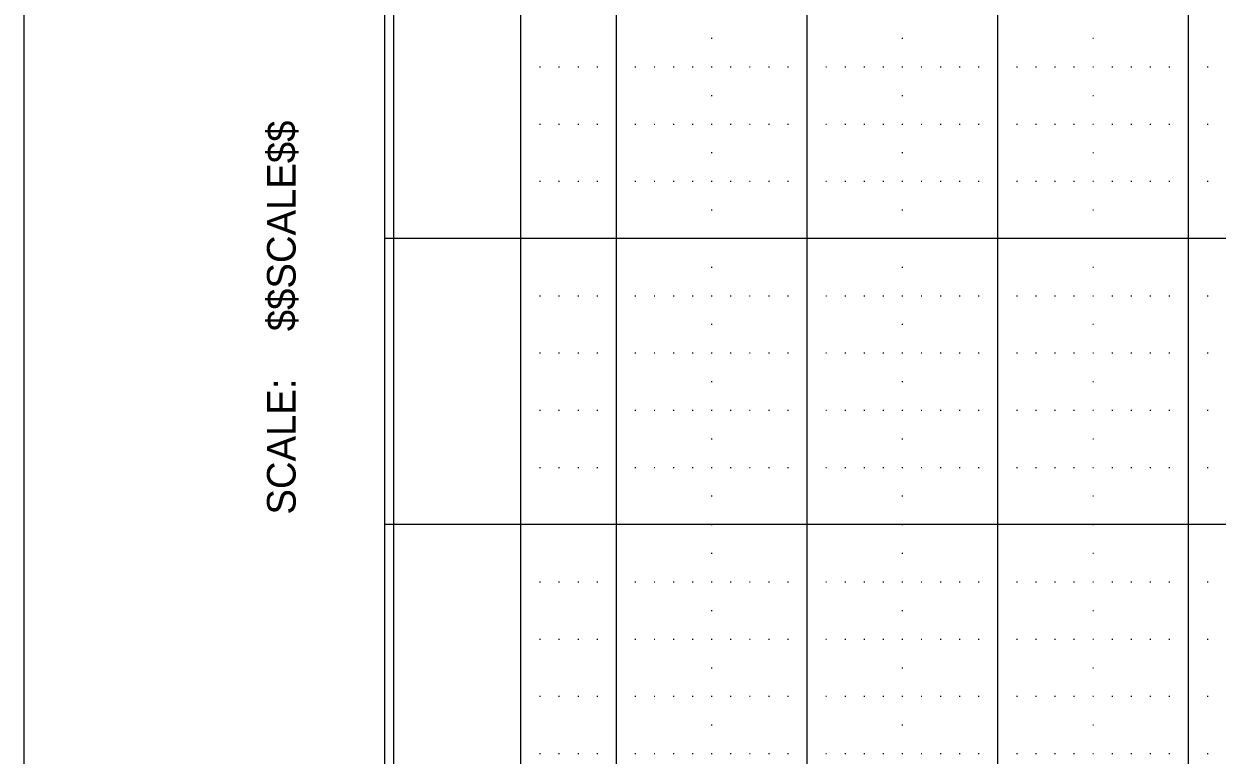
# Model space of a CAD drawing. Extents: x -1.3 to 32, y -0.2 to 20.7.
# Drawn here: x -1.292 to 2.879, y 2.458 to 5.014 of the extents above; entities that cross this region are included whole.
import ezdxf

# ---------------------------------------------------------------- set-up
doc = ezdxf.new("R2010")
doc.units = 0
for name, color, linetype in [('Level 1', 7, 'Continuous'), ('Level 37', 7, 'Continuous'), ('Level 4', 7, 'Continuous'), ('Level 5', 7, 'Continuous'), ('Level 62', 7, 'Continuous'), ('Level 63', 7, 'Continuous')]:
    doc.layers.add(name, color=color, linetype=linetype)

msp = doc.modelspace()

# ---------------------------------------------------------------- linework, layer by layer
at = {"layer": 'Level 1'}
msp.add_line((-0.03, -0.03), (-0.03, 20.516), dxfattribs=at)
at = {"layer": 'Level 37'}
msp.add_line((0.4457, 0.2635), (0.4457, 10.264), dxfattribs=at)
at = {"layer": 'Level 4'}
for p, q in [((0.4457, 0.264), (0.4457, 10.264)), ((0.779, 0.264), (0.779, 10.264)), ((1.4457, 0.264), (1.4457, 10.264)), ((2.1123, 0.264), (2.1123, 10.264)), ((2.779, 0.264), (2.779, 10.264)), ((31.588, 4.264), (-0.03, 4.264)), ((31.588, 3.264), (-0.03, 3.264))]:
    msp.add_line(p, q, dxfattribs=at)
at = {"layer": 'Level 5'}
for p, q in [((1.1107, 4.964), (1.114, 4.964)), ((1.7773, 4.964), (1.7807, 4.964)), ((2.444, 4.964), (2.4473, 4.964)), ((0.5107, 4.864), (0.514, 4.864)), ((0.5773, 4.864), (0.5807, 4.864)), ((0.644, 4.864), (0.6473, 4.864)), ((0.7107, 4.864), (0.714, 4.864)), ((0.844, 4.864), (0.8473, 4.864)), ((0.9107, 4.864), (0.914, 4.864)), ((0.9773, 4.864), (0.9807, 4.864)), ((1.044, 4.864), (1.0473, 4.864)), ((1.1107, 4.864), (1.114, 4.864)), ((1.1773, 4.864), (1.1807, 4.864)), ((1.244, 4.864), (1.2473, 4.864)), ((1.3107, 4.864), (1.314, 4.864)), ((1.3773, 4.864), (1.3807, 4.864)), ((1.5107, 4.864), (1.514, 4.864)), ((1.5773, 4.864), (1.5807, 4.864)), ((1.644, 4.864), (1.6473, 4.864)), ((1.7107, 4.864), (1.714, 4.864)), ((1.7773, 4.864), (1.7807, 4.864)), ((1.844, 4.864), (1.8473, 4.864)), ((1.9107, 4.864), (1.914, 4.864)), ((1.9773, 4.864), (1.9807, 4.864)), ((2.044, 4.864), (2.0473, 4.864)), ((2.1773, 4.864), (2.1807, 4.864)), ((2.244, 4.864), (2.2473, 4.864)), ((2.3107, 4.864), (2.314, 4.864)), ((2.3773, 4.864), (2.3807, 4.864)), ((2.444, 4.864), (2.4473, 4.864)), ((2.5107, 4.864), (2.514, 4.864)), ((2.5773, 4.864), (2.5807, 4.864)), ((2.644, 4.864), (2.6473, 4.864)), ((2.7107, 4.864), (2.714, 4.864)), ((2.844, 4.864), (2.8473, 4.864)), ((1.1107, 4.764), (1.114, 4.764)), ((1.7773, 4.764), (1.7807, 4.764)), ((2.444, 4.764), (2.4473, 4.764)), ((0.5107, 4.664), (0.514, 4.664)), ((0.5773, 4.664), (0.5807, 4.664)), ((0.644, 4.664), (0.6473, 4.664)), ((0.7107, 4.664), (0.714, 4.664)), ((0.844, 4.664), (0.8473, 4.664)), ((0.9107, 4.664), (0.914, 4.664)), ((0.9773, 4.664), (0.9807, 4.664)), ((1.044, 4.664), (1.0473, 4.664)), ((1.1107, 4.664), (1.114, 4.664)), ((1.1773, 4.664), (1.1807, 4.664)), ((1.244, 4.664), (1.2473, 4.664)), ((1.3107, 4.664), (1.314, 4.664)), ((1.3773, 4.664), (1.3807, 4.664)), ((1.5107, 4.664), (1.514, 4.664)), ((1.5773, 4.664), (1.5807, 4.664)), ((1.644, 4.664), (1.6473, 4.664)), ((1.7107, 4.664), (1.714, 4.664)), ((1.7773, 4.664), (1.7807, 4.664)), ((1.844, 4.664), (1.8473, 4.664)), ((1.9107, 4.664), (1.914, 4.664)), ((1.9773, 4.664), (1.9807, 4.664)), ((2.044, 4.664), (2.0473, 4.664)), ((2.1773, 4.664), (2.1807, 4.664)), ((2.244, 4.664), (2.2473, 4.664)), ((2.3107, 4.664), (2.314, 4.664)), ((2.3773, 4.664), (2.3807, 4.664)), ((2.444, 4.664), (2.4473, 4.664)), ((2.5107, 4.664), (2.514, 4.664)), ((2.5773, 4.664), (2.5807, 4.664)), ((2.644, 4.664), (2.6473, 4.664)), ((2.7107, 4.664), (2.714, 4.664)), ((2.844, 4.664), (2.8473, 4.664)), ((1.1107, 4.564), (1.114, 4.564)), ((1.7773, 4.564), (1.7807, 4.564)), ((2.444, 4.564), (2.4473, 4.564)), ((0.5107, 4.464), (0.514, 4.464)), ((0.5773, 4.464), (0.5807, 4.464)), ((0.644, 4.464), (0.6473, 4.464)), ((0.7107, 4.464), (0.714, 4.464)), ((0.844, 4.464), (0.8473, 4.464)), ((0.9107, 4.464), (0.914, 4.464)), ((0.9773, 4.464), (0.9807, 4.464)), ((1.044, 4.464), (1.0473, 4.464)), ((1.1107, 4.464), (1.114, 4.464)), ((1.1773, 4.464), (1.1807, 4.464)), ((1.244, 4.464), (1.2473, 4.464)), ((1.3107, 4.464), (1.314, 4.464)), ((1.3773, 4.464), (1.3807, 4.464)), ((1.5107, 4.464), (1.514, 4.464)), ((1.5773, 4.464), (1.5807, 4.464)), ((1.644, 4.464), (1.6473, 4.464)), ((1.7107, 4.464), (1.714, 4.464)), ((1.7773, 4.464), (1.7807, 4.464)), ((1.844, 4.464), (1.8473, 4.464)), ((1.9107, 4.464), (1.914, 4.464)), ((1.9773, 4.464), (1.9807, 4.464)), ((2.044, 4.464), (2.0473, 4.464)), ((2.1773, 4.464), (2.1807, 4.464)), ((2.244, 4.464), (2.2473, 4.464)), ((2.3107, 4.464), (2.314, 4.464)), ((2.3773, 4.464), (2.3807, 4.464)), ((2.444, 4.464), (2.4473, 4.464)), ((2.5107, 4.464), (2.514, 4.464)), ((2.5773, 4.464), (2.5807, 4.464)), ((2.644, 4.464), (2.6473, 4.464)), ((2.7107, 4.464), (2.714, 4.464)), ((2.844, 4.464), (2.8473, 4.464)), ((1.1107, 4.364), (1.114, 4.364)), ((1.7773, 4.364), (1.7807, 4.364)), ((2.444, 4.364), (2.4473, 4.364)), ((1.1107, 4.164), (1.114, 4.164)), ((1.7773, 4.164), (1.7807, 4.164)), ((2.444, 4.164), (2.4473, 4.164)), ((0.5107, 4.064), (0.514, 4.064)), ((0.5773, 4.064), (0.5807, 4.064)), ((0.644, 4.064), (0.6473, 4.064)), ((0.7107, 4.064), (0.714, 4.064)), ((0.844, 4.064), (0.8473, 4.064)), ((0.9107, 4.064), (0.914, 4.064)), ((0.9773, 4.064), (0.9807, 4.064)), ((1.044, 4.064), (1.0473, 4.064)), ((1.1107, 4.064), (1.114, 4.064)), ((1.1773, 4.064), (1.1807, 4.064)), ((1.244, 4.064), (1.2473, 4.064)), ((1.3107, 4.064), (1.314, 4.064)), ((1.3773, 4.064), (1.3807, 4.064)), ((1.5107, 4.064), (1.514, 4.064)), ((1.5773, 4.064), (1.5807, 4.064)), ((1.644, 4.064), (1.6473, 4.064)), ((1.7107, 4.064), (1.714, 4.064)), ((1.7773, 4.064), (1.7807, 4.064)), ((1.844, 4.064), (1.8473, 4.064)), ((1.9107, 4.064), (1.914, 4.064)), ((1.9773, 4.064), (1.9807, 4.064)), ((2.044, 4.064), (2.0473, 4.064)), ((2.1773, 4.064), (2.1807, 4.064)), ((2.244, 4.064), (2.2473, 4.064)), ((2.3107, 4.064), (2.314, 4.064)), ((2.3773, 4.064), (2.3807, 4.064)), ((2.444, 4.064), (2.4473, 4.064)), ((2.5107, 4.064), (2.514, 4.064)), ((2.5773, 4.064), (2.5807, 4.064)), ((2.644, 4.064), (2.6473, 4.064)), ((2.7107, 4.064), (2.714, 4.064)), ((2.844, 4.064), (2.8473, 4.064)), ((1.1107, 3.964), (1.114, 3.964)), ((1.7773, 3.964), (1.7807, 3.964)), ((2.444, 3.964), (2.4473, 3.964)), ((0.5107, 3.864), (0.514, 3.864)), ((0.5773, 3.864), (0.5807, 3.864)), ((0.644, 3.864), (0.6473, 3.864)), ((0.7107, 3.864), (0.714, 3.864)), ((0.844, 3.864), (0.8473, 3.864)), ((0.9107, 3.864), (0.914, 3.864)), ((0.9773, 3.864), (0.9807, 3.864)), ((1.044, 3.864), (1.0473, 3.864)), ((1.1107, 3.864), (1.114, 3.864)), ((1.1773, 3.864), (1.1807, 3.864)), ((1.244, 3.864), (1.2473, 3.864)), ((1.3107, 3.864), (1.314, 3.864)), ((1.3773, 3.864), (1.3807, 3.864)), ((1.5107, 3.864), (1.514, 3.864)), ((1.5773, 3.864), (1.5807, 3.864)), ((1.644, 3.864), (1.6473, 3.864)), ((1.7107, 3.864), (1.714, 3.864)), ((1.7773, 3.864), (1.7807, 3.864)), ((1.844, 3.864), (1.8473, 3.864)), ((1.9107, 3.864), (1.914, 3.864)), ((1.9773, 3.864), (1.9807, 3.864)), ((2.044, 3.864), (2.0473, 3.864)), ((2.1773, 3.864), (2.1807, 3.864)), ((2.244, 3.864), (2.2473, 3.864)), ((2.3107, 3.864), (2.314, 3.864)), ((2.3773, 3.864), (2.3807, 3.864)), ((2.444, 3.864), (2.4473, 3.864)), ((2.5107, 3.864), (2.514, 3.864)), ((2.5773, 3.864), (2.5807, 3.864)), ((2.644, 3.864), (2.6473, 3.864)), ((2.7107, 3.864), (2.714, 3.864)), ((2.844, 3.864), (2.8473, 3.864)), ((1.1107, 3.764), (1.114, 3.764)), ((1.7773, 3.764), (1.7807, 3.764)), ((2.444, 3.764), (2.4473, 3.764)), ((0.5107, 3.664), (0.514, 3.664)), ((0.5773, 3.664), (0.5807, 3.664)), ((0.644, 3.664), (0.6473, 3.664)), ((0.7107, 3.664), (0.714, 3.664)), ((0.844, 3.664), (0.8473, 3.664)), ((0.9107, 3.664), (0.914, 3.664)), ((0.9773, 3.664), (0.9807, 3.664)), ((1.044, 3.664), (1.0473, 3.664)), ((1.1107, 3.664), (1.114, 3.664)), ((1.1773, 3.664), (1.1807, 3.664)), ((1.244, 3.664), (1.2473, 3.664)), ((1.3107, 3.664), (1.314, 3.664)), ((1.3773, 3.664), (1.3807, 3.664)), ((1.5107, 3.664), (1.514, 3.664)), ((1.5773, 3.664), (1.5807, 3.664)), ((1.644, 3.664), (1.6473, 3.664)), ((1.7107, 3.664), (1.714, 3.664)), ((1.7773, 3.664), (1.7807, 3.664)), ((1.844, 3.664), (1.8473, 3.664)), ((1.9107, 3.664), (1.914, 3.664)), ((1.9773, 3.664), (1.9807, 3.664)), ((2.044, 3.664), (2.0473, 3.664)), ((2.1773, 3.664), (2.1807, 3.664)), ((2.244, 3.664), (2.2473, 3.664)), ((2.3107, 3.664), (2.314, 3.664)), ((2.3773, 3.664), (2.3807, 3.664)), ((2.444, 3.664), (2.4473, 3.664)), ((2.5107, 3.664), (2.514, 3.664)), ((2.5773, 3.664), (2.5807, 3.664)), ((2.644, 3.664), (2.6473, 3.664)), ((2.7107, 3.664), (2.714, 3.664)), ((2.844, 3.664), (2.8473, 3.664)), ((1.1107, 3.564), (1.114, 3.564)), ((1.7773, 3.564), (1.7807, 3.564)), ((2.444, 3.564), (2.4473, 3.564)), ((0.5107, 3.464), (0.514, 3.464)), ((0.5773, 3.464), (0.5807, 3.464)), ((0.644, 3.464), (0.6473, 3.464)), ((0.7107, 3.464), (0.714, 3.464)), ((0.844, 3.464), (0.8473, 3.464)), ((0.9107, 3.464), (0.914, 3.464)), ((0.9773, 3.464), (0.9807, 3.464)), ((1.044, 3.464), (1.0473, 3.464)), ((1.1107, 3.464), (1.114, 3.464)), ((1.1773, 3.464), (1.1807, 3.464)), ((1.244, 3.464), (1.2473, 3.464)), ((1.3107, 3.464), (1.314, 3.464)), ((1.3773, 3.464), (1.3807, 3.464)), ((1.5107, 3.464), (1.514, 3.464)), ((1.5773, 3.464), (1.5807, 3.464)), ((1.644, 3.464), (1.6473, 3.464)), ((1.7107, 3.464), (1.714, 3.464)), ((1.7773, 3.464), (1.7807, 3.464)), ((1.844, 3.464), (1.8473, 3.464)), ((1.9107, 3.464), (1.914, 3.464)), ((1.9773, 3.464), (1.9807, 3.464)), ((2.044, 3.464), (2.0473, 3.464)), ((2.1773, 3.464), (2.1807, 3.464)), ((2.244, 3.464), (2.2473, 3.464)), ((2.3107, 3.464), (2.314, 3.464)), ((2.3773, 3.464), (2.3807, 3.464)), ((2.444, 3.464), (2.4473, 3.464)), ((2.5107, 3.464), (2.514, 3.464)), ((2.5773, 3.464), (2.5807, 3.464)), ((2.644, 3.464), (2.6473, 3.464)), ((2.7107, 3.464), (2.714, 3.464)), ((2.844, 3.464), (2.8473, 3.464)), ((1.1107, 3.364), (1.114, 3.364)), ((1.7773, 3.364), (1.7807, 3.364)), ((2.444, 3.364), (2.4473, 3.364)), ((1.1107, 3.264), (1.114, 3.264)), ((1.7773, 3.264), (1.7807, 3.264)), ((2.444, 3.264), (2.4473, 3.264)), ((1.1107, 3.164), (1.114, 3.164)), ((1.7773, 3.164), (1.7807, 3.164)), ((2.444, 3.164), (2.4473, 3.164)), ((0.5107, 3.064), (0.514, 3.064)), ((0.5773, 3.064), (0.5807, 3.064)), ((0.644, 3.064), (0.6473, 3.064)), ((0.7107, 3.064), (0.714, 3.064)), ((0.844, 3.064), (0.8473, 3.064)), ((0.9107, 3.064), (0.914, 3.064)), ((0.9773, 3.064), (0.9807, 3.064)), ((1.044, 3.064), (1.0473, 3.064)), ((1.1107, 3.064), (1.114, 3.064)), ((1.1773, 3.064), (1.1807, 3.064)), ((1.244, 3.064), (1.2473, 3.064)), ((1.3107, 3.064), (1.314, 3.064)), ((1.3773, 3.064), (1.3807, 3.064)), ((1.5107, 3.064), (1.514, 3.064)), ((1.5773, 3.064), (1.5807, 3.064)), ((1.644, 3.064), (1.6473, 3.064)), ((1.7107, 3.064), (1.714, 3.064)), ((1.7773, 3.064), (1.7807, 3.064)), ((1.844, 3.064), (1.8473, 3.064)), ((1.9107, 3.064), (1.914, 3.064)), ((1.9773, 3.064), (1.9807, 3.064)), ((2.044, 3.064), (2.0473, 3.064)), ((2.1773, 3.064), (2.1807, 3.064)), ((2.244, 3.064), (2.2473, 3.064)), ((2.3107, 3.064), (2.314, 3.064)), ((2.3773, 3.064), (2.3807, 3.064)), ((2.444, 3.064), (2.4473, 3.064)), ((2.5107, 3.064), (2.514, 3.064)), ((2.5773, 3.064), (2.5807, 3.064)), ((2.644, 3.064), (2.6473, 3.064)), ((2.7107, 3.064), (2.714, 3.064)), ((2.844, 3.064), (2.8473, 3.064)), ((1.1107, 2.964), (1.114, 2.964)), ((1.7773, 2.964), (1.7807, 2.964)), ((2.444, 2.964), (2.4473, 2.964)), ((0.5107, 2.864), (0.514, 2.864)), ((0.5773, 2.864), (0.5807, 2.864)), ((0.644, 2.864), (0.6473, 2.864)), ((0.7107, 2.864), (0.714, 2.864)), ((0.844, 2.864), (0.8473, 2.864)), ((0.9107, 2.864), (0.914, 2.864)), ((0.9773, 2.864), (0.9807, 2.864)), ((1.044, 2.864), (1.0473, 2.864)), ((1.1107, 2.864), (1.114, 2.864)), ((1.1773, 2.864), (1.1807, 2.864)), ((1.244, 2.864), (1.2473, 2.864)), ((1.3107, 2.864), (1.314, 2.864)), ((1.3773, 2.864), (1.3807, 2.864)), ((1.5107, 2.864), (1.514, 2.864)), ((1.5773, 2.864), (1.5807, 2.864)), ((1.644, 2.864), (1.6473, 2.864)), ((1.7107, 2.864), (1.714, 2.864)), ((1.7773, 2.864), (1.7807, 2.864)), ((1.844, 2.864), (1.8473, 2.864)), ((1.9107, 2.864), (1.914, 2.864)), ((1.9773, 2.864), (1.9807, 2.864)), ((2.044, 2.864), (2.0473, 2.864)), ((2.1773, 2.864), (2.1807, 2.864)), ((2.244, 2.864), (2.2473, 2.864)), ((2.3107, 2.864), (2.314, 2.864)), ((2.3773, 2.864), (2.3807, 2.864)), ((2.444, 2.864), (2.4473, 2.864)), ((2.5107, 2.864), (2.514, 2.864)), ((2.5773, 2.864), (2.5807, 2.864)), ((2.644, 2.864), (2.6473, 2.864)), ((2.7107, 2.864), (2.714, 2.864)), ((2.844, 2.864), (2.8473, 2.864)), ((1.1107, 2.764), (1.114, 2.764)), ((1.7773, 2.764), (1.7807, 2.764)), ((2.444, 2.764), (2.4473, 2.764)), ((0.5107, 2.664), (0.514, 2.664)), ((0.5773, 2.664), (0.5807, 2.664)), ((0.644, 2.664), (0.6473, 2.664)), ((0.7107, 2.664), (0.714, 2.664)), ((0.844, 2.664), (0.8473, 2.664)), ((0.9107, 2.664), (0.914, 2.664)), ((0.9773, 2.664), (0.9807, 2.664)), ((1.044, 2.664), (1.0473, 2.664)), ((1.1107, 2.664), (1.114, 2.664)), ((1.1773, 2.664), (1.1807, 2.664)), ((1.244, 2.664), (1.2473, 2.664)), ((1.3107, 2.664), (1.314, 2.664)), ((1.3773, 2.664), (1.3807, 2.664)), ((1.5107, 2.664), (1.514, 2.664)), ((1.5773, 2.664), (1.5807, 2.664)), ((1.644, 2.664), (1.6473, 2.664)), ((1.7107, 2.664), (1.714, 2.664)), ((1.7773, 2.664), (1.7807, 2.664)), ((1.844, 2.664), (1.8473, 2.664)), ((1.9107, 2.664), (1.914, 2.664)), ((1.9773, 2.664), (1.9807, 2.664)), ((2.044, 2.664), (2.0473, 2.664)), ((2.1773, 2.664), (2.1807, 2.664)), ((2.244, 2.664), (2.2473, 2.664)), ((2.3107, 2.664), (2.314, 2.664)), ((2.3773, 2.664), (2.3807, 2.664)), ((2.444, 2.664), (2.4473, 2.664)), ((2.5107, 2.664), (2.514, 2.664)), ((2.5773, 2.664), (2.5807, 2.664)), ((2.644, 2.664), (2.6473, 2.664)), ((2.7107, 2.664), (2.714, 2.664)), ((2.844, 2.664), (2.8473, 2.664)), ((1.1107, 2.564), (1.114, 2.564)), ((1.7773, 2.564), (1.7807, 2.564)), ((2.444, 2.564), (2.4473, 2.564)), ((0.5107, 2.464), (0.514, 2.464)), ((0.5773, 2.464), (0.5807, 2.464)), ((0.644, 2.464), (0.6473, 2.464)), ((0.7107, 2.464), (0.714, 2.464)), ((0.844, 2.464), (0.8473, 2.464)), ((0.9107, 2.464), (0.914, 2.464)), ((0.9773, 2.464), (0.9807, 2.464)), ((1.044, 2.464), (1.0473, 2.464)), ((1.1107, 2.464), (1.114, 2.464)), ((1.1773, 2.464), (1.1807, 2.464)), ((1.244, 2.464), (1.2473, 2.464)), ((1.3107, 2.464), (1.314, 2.464)), ((1.3773, 2.464), (1.3807, 2.464)), ((1.5107, 2.464), (1.514, 2.464)), ((1.5773, 2.464), (1.5807, 2.464)), ((1.644, 2.464), (1.6473, 2.464)), ((1.7107, 2.464), (1.714, 2.464)), ((1.7773, 2.464), (1.7807, 2.464)), ((1.844, 2.464), (1.8473, 2.464)), ((1.9107, 2.464), (1.914, 2.464)), ((1.9773, 2.464), (1.9807, 2.464)), ((2.044, 2.464), (2.0473, 2.464)), ((2.1773, 2.464), (2.1807, 2.464)), ((2.244, 2.464), (2.2473, 2.464)), ((2.3107, 2.464), (2.314, 2.464)), ((2.3773, 2.464), (2.3807, 2.464)), ((2.444, 2.464), (2.4473, 2.464)), ((2.5107, 2.464), (2.514, 2.464)), ((2.5773, 2.464), (2.5807, 2.464)), ((2.644, 2.464), (2.6473, 2.464)), ((2.7107, 2.464), (2.714, 2.464)), ((2.844, 2.464), (2.8473, 2.464))]:
    msp.add_line(p, q, dxfattribs=at)
at = {"layer": 'Level 62'}
msp.add_line((0, 10.294), (0, 0.6734), dxfattribs=at)
at = {"layer": 'Level 63'}
msp.add_lwpolyline([(-1.292, -0.2295), (32.038, -0.2295), (32.038, 20.7175), (-1.292, 20.7175)], close=True, dxfattribs=at)

# ---------------------------------------------------------------- texts
at = {"layer": 'Level 1'}
for s, p in [('$$SCALE$$', (-0.342, 3.94)), ('SCALE:', (-0.342, 3.299))]:
    msp.add_text(s, height=0.1, rotation=90, dxfattribs=at).set_placement(p)

doc.saveas('drawing.dxf')
